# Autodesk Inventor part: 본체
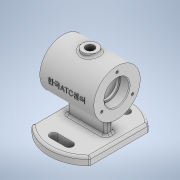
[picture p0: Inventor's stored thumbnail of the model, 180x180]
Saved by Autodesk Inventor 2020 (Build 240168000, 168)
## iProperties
Created: 2021-09
Part Number: 본체
Material: 일반
Document SubType Name: Modeling
Designer: Administrator
Density: 1 g/cm^3
Appearance: 기본값
Author: Administrator
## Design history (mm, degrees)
sketch "스케치1"
  geometry: L1 (37.5, -37.682)-(37.5, 37.682); L2 (-37.5, -37.682)-(-37.5, 37.682); L3 (37.5, 0)-(-37.5, 0); A1 r 53.162 centre (0, 0) between (37.5, 37.682) and (-37.5, 37.682); A2 r 53.162 centre (0, 0) between (-37.5, -37.682) and (37.5, -37.682); 2 further points
  constraints: 6 end point, 4 point on circle, 3 midpoint, 2 centre point, 2 coincident, 2 vertical
  dimensions: "d1" = 75 distance between parallel lines of L2 L1
extrude "돌출1" new body sketch "스케치1" distance "d2" = 10; taper "d3" = 0 deg
sketch "스케치2"
  geometry: C1 r 30 at (62, 0); 1 further point
  constraints: 1 centre point, 1 horizontal alignment
  dimensions: "d4" = 62 distance of C1.centre point (0, 0); "d11" = 60 diameter of C1
extrude "돌출2" join sketch "스케치2" stored distance "d5" = 70; taper "d6" = 0 deg
sketch "스케치3"
  geometry: L1 (62, 0)-(95, 0); C1 r 30 at (62, 0) reference; 1 further point
  constraints: 2 end point, 1 horizontal
  dimensions: "d7" = 33 distance of L1.start L1.end
node "작업 평면1"
sketch "스케치4"
  geometry: C1 r 10 at (0, 0); 2 further points
  constraints: 1 centre point, 1 coincident
  dimensions: "d8" = 20 diameter of C1
extrude "돌출3" join sketch "스케치4" stored distance "d9" = 70; taper "d10" = 0 deg; dims "d7" = 33, "d8" = 20
sketch "스케치5"
  geometry: C1 r 30 at (0, 0) reference; 2 further points
  constraints: 1 coincident
hole "구멍1" sketch "스케치5" at (0, 0) diameter "d12" = 28; stored, may be unused: countersink angle "d16" = 90 deg, drill point angle "d18" = 118 deg; dims "d13" = 6, "d14" = 32, "d15" = 12, "d17" = 8
sketch "스케치6"
  geometry: L1 (-23, 76)-(-23, 48) reference; L2 (-23, 62)-(23, 62); L3 (-20, 87)-(20, 87); L4 (-20, 87)-(-20, 62); L5 (20, 87)-(20, 62); 3 further points
  constraints: 8 end point, 3 midpoint, 2 horizontal, 2 perpendicular, 2 point on line, 1 vertical alignment
  dimensions: "d19" = 40 distance of L3.start L3.end; "d21" = 50 diameter of L3 L2
revolve "회전1" sketch "스케치6" stored, may be unused: angle "d22" = 90 deg
sketch "스케치7"
  geometry: L1 (-25, 35.562)-(25, 35.562); L2 (25, 35.562)-(25, 5.882); L3 (25, 5.882)-(-25, 5.882); L4 (-25, 5.882)-(-25, 35.562); L5 (-25, 35.562)-(25, 5.882); L6 (25, 35.562)-(-25, 5.882); L7 (-37.5, 0)-(-37.5, 10) reference; 2 further points
  constraints: 12 end point, 2 midpoint, 2 parallel, 1 horizontal, 1 perpendicular
  dimensions: "d23" = 50 distance of L2.end L3.end; "d24" = 12.5 distance between parallel lines of L4 L7
extrude "돌출4" join sketch "스케치7" stored distance "d25" = 10; taper "d26" = 0 deg
sketch "스케치8"
  geometry: C1 r 10 at (0, 0) reference; 2 further points
  constraints: 1 coincident
hole "구멍2" sketch "스케치8" at (0, 0) diameter "d27" = 10.917; stored, may be unused: countersink angle "d31" = 90 deg, drill point angle "d33" = 118 deg; dims "d28" = 24, "d29" = 32, "d30" = 12, "d32" = 29.1
sketch "스케치9"
  geometry: C1 r 30 at (0, 0) reference; 2 further points
  constraints: 1 vertical alignment
  dimensions: "d41" = 23 distance of C1.centre point (0, 23)
hole "구멍3" sketch "스케치9" at (0, 23) diameter "d34" = 3.242; stored, may be unused: countersink angle "d38" = 90 deg, drill point angle "d40" = 118 deg; dims "d35" = 8, "d36" = 32, "d37" = 12, "d39" = 10
fillet "모깎기1" dims "d45" = 0.3
fillet "모깎기2" dims "d46" = 3
fillet "모깎기3" dims "d47" = 3
chamfer "모따기1" distance "d48" = 1; stored, may be unused: second distance "d49" = 2, angle "d50" = 45 deg
sketch "스케치10"
  geometry: L1 (-10, 37)-(10, 37); L2 (-10, 32)-(10, 32); L3 (10, 42)-(-10, 42); A1 r 5 centre (-10, 37) between (-10, 42) and (-10, 32); A2 r 5 centre (10, 37) between (10, 32) and (10, 42); 2 further points
  constraints: 8 end point, 4 point on circle, 4 tangent, 2 centre point, 1 horizontal, 1 midpoint, 1 parallel, 1 vertical alignment
  dimensions: "d51" = 20 distance of L1.start L1.end; "d52" = 5 radius of A1; "d53" = 37 distance from line of point (0, 0) L1
extrude "돌출5" cut sketch "스케치10" extent not by distance; stored distance "d54" = 0; taper "d55" = 0 deg
node "작업 평면2"
sketch "스케치11"
  geometry: L1 (-35, 30)-(-35, -30) reference; L2 (-35, 30)-(35, 30) reference; 2 further points
  constraints: 1 other
  dimensions: "d56" = 35 distance from line of L1 point (0, 0); "d57" = 30 distance from line of point (0, 0) L2
feature "엠보싱1" sketch "스케치11" dims "d11" = 60, "d58" = 0.5, "d59" = 0
node "솔리드1"
mirror "미러1"
pattern_circular "원형 패턴1" dims angle "d43" = 360 deg
mirror "미러2"
mirror "미러3"
feature "A9D066F2-1C7D-4E18-AEED-F7BC21143FA4" dims "d12" = 28, "d13" = 6, "d14" = 32, "d15" = 12, "d16" = 90 deg, "d17" = 8, "d18" = 118 deg
other parameters: "d0" = 105
